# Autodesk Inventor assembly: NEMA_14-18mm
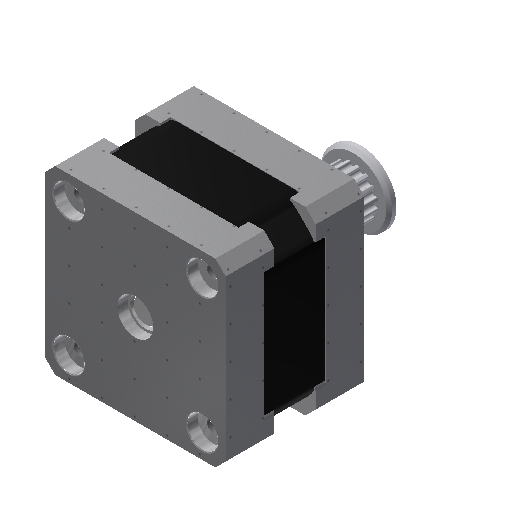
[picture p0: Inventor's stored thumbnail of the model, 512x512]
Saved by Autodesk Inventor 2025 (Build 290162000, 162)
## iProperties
Created: 2019-11
Part Number: NEMA_14-18mm
Material: Générique
Document SubType Name: Assembly
Designer: thoma
Author: thoma
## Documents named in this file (4)
- C:\Users\R5800u\Desktop\nema14\NEMA_14-18mm.iam
- C:\Users\R5800u\Desktop\nema14\NEMA_14HM11-0404S_BODY.ipt
- C:\Users\R5800u\Desktop\nema14\NEMA_14HM11-0404S_SHAFT.ipt
- C:\Users\R5800u\Desktop\nema14\GT2 16 Teeth Free Pulley.ipt
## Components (3 placed, 3 different names)
1. NEMA_14HM11-0404S:1 — Affleurement:2, Placage:2, Placage:3, Affleurement:3, Rotazionale:1
2. NEMA_14HM11-0404S_SHAFT:1 — Affleurement:3
3. GT2 16 Teeth Free Pulley:1 — Rotazionale:1
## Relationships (5: Flush 2, Mate 2, RevoluteJoint 1)
- Affleurement:2 [Flush]: NEMA_14HM11-0404S:1
- Placage:2 [Mate]: NEMA_14HM11-0404S:1
- Placage:3 [Mate]: NEMA_14HM11-0404S:1
- Affleurement:3 [Flush]: NEMA_14HM11-0404S:1 ↔ NEMA_14HM11-0404S_SHAFT:1
- Rotazionale:1 [RevoluteJoint]: NEMA_14HM11-0404S:1 ↔ GT2 16 Teeth Free Pulley:1
